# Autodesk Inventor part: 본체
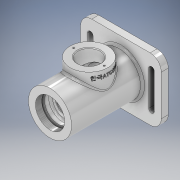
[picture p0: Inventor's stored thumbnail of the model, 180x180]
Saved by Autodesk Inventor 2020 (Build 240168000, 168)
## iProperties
Created: 2021-07
Part Number: 본체
Material: 일반
Document SubType Name: Modeling
Designer: MIRAE
Density: 1 g/cm^3
Appearance: 알루미늄 - 연마
Author: MIRAE
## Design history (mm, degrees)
sketch "스케치1"
  geometry: L1 (0, 0)-(0, 31); L2 (0, 31)-(102, 31); L3 (115, 0)-(0, 0); L4 (102, 31)-(102, 0)
  constraints: 8 end point, 2 perpendicular, 1 point on line, 1 vertical
  dimensions: "d4" = 62 diameter of L2 L3; "d5" = 102 distance of L1.end L2.end
revolve "회전1" sketch "스케치1" stored, may be unused: angle "d6" = 90 deg
sketch "스케치2"
  geometry: L1 (-58, -45)-(58, -45); L2 (58, -45)-(58, 45); L3 (58, 45)-(-58, 45); L4 (-58, 45)-(-58, -45); L5 (-58, -45)-(58, 45); L6 (58, -45)-(-58, 45); 1 further point
  constraints: 12 end point, 2 midpoint, 2 parallel, 1 horizontal, 1 perpendicular
  dimensions: "d7" = 116 distance of L2.end L3.end; "d8" = 90 distance of L1.end L2.end
extrude "돌출1" join sketch "스케치2" distance "d9" = 10; taper "d10" = 0 deg
sketch "스케치3"
  geometry: C1 r 35 at (0, 0); 1 further point
  constraints: 1 centre point, 1 coincident
  dimensions: "d11" = 70 diameter of C1
extrude "돌출2" join sketch "스케치3" distance "d12" = 3; taper "d13" = 0 deg
sketch "스케치4"
  geometry: L1 (0, 0)-(115, 0); L2 (0, -31)-(0, 31) reference; L3 (102, -31)-(102, 31) reference; L4 (102, -45)-(102, 45) reference; L5 (102, 45)-(112, 45) reference; L6 (112, -45)-(112, 45) reference; L7 (102, -45)-(112, -45) reference; L8 (115, -35)-(115, 35) reference; L9 (112, 35)-(112, -35) reference; L10 (0, 21)-(9, 21); L11 (9, 21)-(9, 24); L12 (9, 24)-(12, 24); L13 (12, 24)-(12, 20); L14 (21, 20)-(21, 17.5); L15 (21, 17.5)-(24.25, 17.5); L16 (24.25, 17.5)-(24.25, 18.5); L17 (24.25, 18.5)-(26, 18.5); L18 (26, 18.5)-(26, 17.5); L19 (26, 17.5)-(37, 17.5); L20 (37, 17.5)-(37, 26); L21 (37, 26)-(75, 26); L22 (75, 26)-(75, 17.5); L23 (75, 17.5)-(85.7, 17.5); L24 (86, 17.2)-(86, 16); L25 (86, 16)-(88, 16); L26 (91, 13)-(91, 10); L27 (91, 10)-(93.7, 10); L28 (93.7, 10)-(93.7, 12.2); L29 (94, 12.5)-(100.3, 12.5); L30 (100.3, 12.5)-(101, 12.904); L31 (101, 12.904)-(101, 16); L32 (101, 16)-(115, 22); L33 (21, 20)-(12, 20); L34 (0, 31)-(56, 31); A1 r 0.3 centre (94, 12.2) between (94, 12.5) and (93.7, 12.2); A2 r 0.3 centre (85.7, 17.2) between (86, 17.2) and (85.7, 17.5); A3 r 3 centre (88, 13) between (91, 13) and (88, 16); 3 further points
  constraints: 52 end point, 15 perpendicular, 8 point on line, 6 point on circle, 6 tangent, 4 horizontal, 3 centre point, 2 midpoint, 1 equal radius, 1 parallel, 1 vertical, 1 vertical alignment
  dimensions: "d18" = 9 distance of L10.start L10.end; "d19" = 3 distance of L11.end L12.end; "d20" = 21 distance from line of L14.end L2; "d21" = 1.75 distance of L16.end L17.end; "d23" = 11 distance of L18.end L19.end; "d24" = 38 distance of L20.end L21.end; "d25" = 11 distance of L22.end point (86, 17.5); "d26" = 14 distance from line of L8 L31.end; "d27" = 24 distance between parallel lines of L8 L26; "d28" = 30 deg angle of L30 L29; "d29" = 7.3 distance from line of L30.end L28; "d30" = 0.3 radius of A1; "d31" = 48 diameter of L12 L1; "d32" = 42 diameter of L10 L1; "d33" = 40 diameter of L33 L1; "d34" = 35 diameter of L15 L1; "d35" = 52 diameter of L21 L1; "d36" = 20 diameter of L27 L1; "d37" = 32 diameter of L31.end L1; "d38" = 44 diameter of L32.end L1; "d39" = 25 diameter of L29 L1; "d40" = 0.7 horizontal distance of L30.end L29.end; "d42" = 65 distance between parallel lines of L26 L18 (derived); "d43" = 32 diameter of L25 L1; "d44" = 3 radius of A3; "d45" = 1.75 distance between parallel lines of L18 L16 (derived); "d46" = 37 diameter of L17 L1; "d47" = 56 distance of L2.end L34.end
revolve "회전2" sketch "스케치4" stored, may be unused: angle "d48" = 90 deg
feature "스레드1" dims "d49" = 9, "d50" = 0
fillet "모깎기1" dims "d51" = 3
node "작업 평면1"
sketch "스케치5"
  geometry: L1 (0, 31)-(0, -31) reference; C1 r 27 at (-56, 0); 1 further point
  constraints: 1 centre point, 1 horizontal alignment
  dimensions: "d53" = 54 diameter of C1; "d54" = 56 distance from line of C1.centre L1
extrude "돌출3" join sketch "스케치5" stored distance "d55" = 10; taper "d56" = 0 deg
sketch "스케치6"
  geometry: C1 r 27 at (0, 0) reference; 2 further points
  constraints: 1 coincident
hole "구멍1" sketch "스케치6" at (0, 0) diameter "d57" = 32; stored, may be unused: countersink angle "d61" = 90 deg, drill point angle "d63" = 0 deg; dims "d58" = 6, "d59" = 4, "d60" = 2, "d62" = 40
chamfer "모따기1" distance "d64" = 1; stored, may be unused: second distance "d65" = 2, angle "d66" = 45 deg
sketch "스케치7"
  geometry: C1 r 16 at (0, 0) reference; A1 r 22 centre (0, 0) between (0, 22) and (0, -22); 1 further point
  constraints: 2 point on circle, 1 centre point, 1 coincident
  dimensions: "d67" = 44 diameter of A1
hole "구멍2" sketch "스케치7" at (0, 22), (0, -22) diameter "d68" = 2.459; stored, may be unused: countersink angle "d72" = 90 deg, drill point angle "d74" = 118 deg; dims "d69" = 6, "d70" = 4, "d71" = 2, "d73" = 8
fillet "모깎기2" dims "d75" = 16
sketch "스케치8"
  geometry: L1 (-44, 25)-(44, 25); L2 (44, 25)-(44, -25); L3 (44, -25)-(-44, -25); L4 (-44, -25)-(-44, 25); L5 (-44, 25)-(-44, -25); L6 (-48, 25)-(-48, -25); L7 (-40, -25)-(-40, 25); L8 (44, 25)-(44, -25); L9 (40, 25)-(40, -25); L10 (48, -25)-(48, 25); A1 r 4 centre (-44, 25) between (-40, 25) and (-48, 25); A2 r 4 centre (-44, -25) between (-48, -25) and (-40, -25); A3 r 4 centre (44, 25) between (48, 25) and (40, 25); A4 r 4 centre (44, -25) between (40, -25) and (48, -25); 5 further points
  constraints: 24 end point, 8 point on circle, 8 tangent, 5 equal length, 4 centre point, 4 midpoint, 2 perpendicular, 1 horizontal, 1 horizontal alignment, 1 vertical alignment
  dimensions: "d76" = 88 distance of L1.start L1.end; "d77" = 50 distance of L1.end L2.end; "d78" = 4 radius of A3; "d79" = 4 radius of A1
extrude "돌출4" cut sketch "스케치8" extent not by distance; stored distance "d80" = 0; taper "d81" = 0 deg
fillet "모깎기3" dims "d82" = 3
fillet "모깎기4" dims "d83" = 3
node "작업 평면2"
sketch "스케치9"
  geometry: L1 (-24.049, -4.47)-(24.049, -4.47); L2 (24.049, -4.47)-(24.049, -11.53); L3 (24.049, -11.53)-(-24.049, -11.53); L4 (-24.049, -11.53)-(-24.049, -4.47); L5 (-24.049, -4.47)-(24.049, -11.53); L6 (27, 0)-(-27, 0) reference; 3 further points
  constraints: 2 end point, 2 midpoint, 1 vertical alignment, 2 other
  dimensions: "d84" = 8 distance from line of point (0, -8) L6
feature "엠보싱1" sketch "스케치9" dims "d85" = 0.5, "d86" = 0
fillet "모깎기5" dims "d87" = 3
fillet "모깎기6" dims "d88" = 3
chamfer "모따기2" distance "d89" = 1; stored, may be unused: second distance "d90" = 2, angle "d91" = 45 deg
node "솔리드1"
node "투영된 루프1"
node "투영된 루프2"
node "투영된 루프3"
feature "A9D066F2-1C7D-4E18-AEED-F7BC21143FA4" dims "d68" = 2.459, "d69" = 6, "d70" = 4, "d71" = 2, "d72" = 90 deg, "d73" = 8, "d74" = 118 deg
other parameters: "d52" = 42
